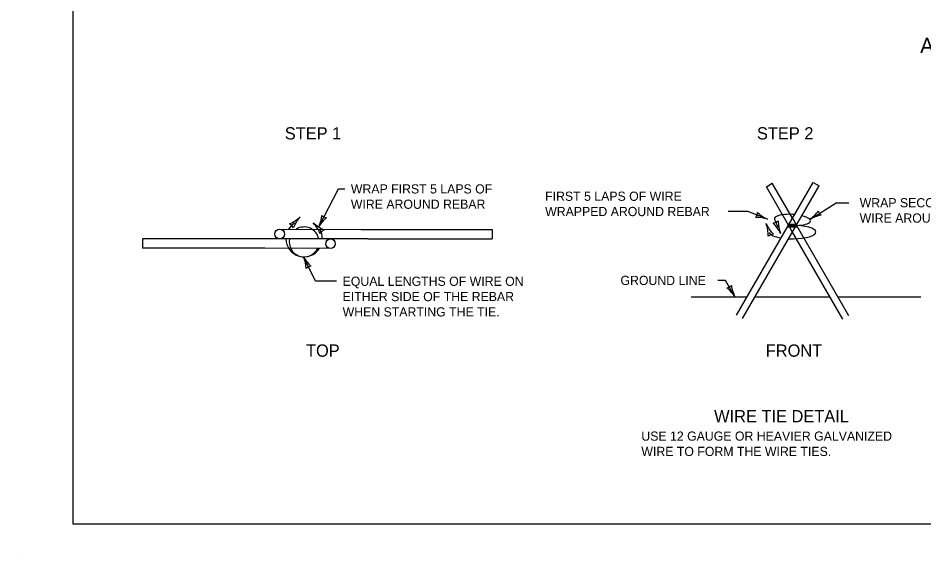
# Model space of a CAD drawing. Extents: x 49991.4 to 50021, y 49987.6 to 50011.4.
# Drawn here: x 49999.02 to 50004.94, y 49987.6 to 49991.1 of the extents above; entities that cross this region are included whole.
import ezdxf

# ---------------------------------------------------------------- set-up
doc = ezdxf.new("R2010")
doc.units = 0
for name, color, linetype in [('Level 1', 7, 'Continuous'), ('Level 2', 7, 'Continuous'), ('Level 3', 7, 'Continuous')]:
    doc.layers.add(name, color=color, linetype=linetype)

msp = doc.modelspace()

# ---------------------------------------------------------------- linework, layer by layer
at = {"layer": 'Level 1'}
for p, q in [((50003.7146, 49989.1648), (50004.2146, 49990.0309)), ((50003.7534, 49989.1424), (50004.2534, 49990.0085)), ((50003.9087, 49990.0035), (50003.9475, 49990.0259)), ((50004.0538, 49989.7523), (50003.9087, 49990.0035)), ((50004.0796, 49989.797), (50003.9475, 49990.0259)), ((50004.2146, 49990.0309), (50004.2534, 49990.0085)), ((50004.0499, 49989.7589), (50004.1093, 49989.7589)), ((50004.0796, 49989.797), (50004.1055, 49989.7522)), ((50000.732, 49989.7258), (50001.2631, 49989.7245)), ((50001.2631, 49989.7245), (50002.1199, 49989.7245)), ((50002.1199, 49989.7245), (50002.1199, 49989.662)), ((50004.0479, 49989.7422), (50004.1113, 49989.7422)), ((50004.0504, 49989.7464), (50004.1088, 49989.7464)), ((50004.0524, 49989.7547), (50004.1069, 49989.7547)), ((50004.0527, 49989.7505), (50004.1065, 49989.7505)), ((50004.0796, 49989.7074), (50004.0538, 49989.7523)), ((50004.4087, 49989.1374), (50004.0796, 49989.7074)), ((50004.4475, 49989.1598), (50004.1055, 49989.7522)), ((50000.627, 49989.6629), (49999.837, 49989.6629)), ((49999.837, 49989.6629), (49999.837, 49989.6019)), ((50001.0638, 49989.6625), (50000.627, 49989.6629)), ((50001.3067, 49989.662), (50000.7322, 49989.6633)), ((50001.3067, 49989.662), (50002.1199, 49989.662)), ((50000.6357, 49989.6019), (49999.837, 49989.6019)), ((50001.0638, 49989.6), (50000.6357, 49989.6019)), ((50003.4178, 49989.2845), (50003.7837, 49989.2845)), ((50003.8354, 49989.2845), (50004.3238, 49989.2845)), ((50004.3755, 49989.2845), (50004.916, 49989.2845)), ((49999.0245, 49987.5988), (49999.0245, 49987.5988))]:
    msp.add_line(p, q, dxfattribs=at)
msp.add_lwpolyline([(49999.3835, 49998.9992), (50016.7501, 49998.9992), (50016.7501, 49987.7988), (49999.3835, 49987.7988)], close=True, dxfattribs=at)
for centre in [(50000.732, 49989.6945), (50001.0638, 49989.6313)]:
    msp.add_circle(centre, 0.0312, dxfattribs=at)
for centre, radius, start, end in [((50000.8914, 49989.6644), 0.1189, 121.84931, 149.00193), ((50000.7017, 49989.9834), 0.2408, 292.89815, 313.08165), ((50000.7687, 49989.7085), 0.0593, 27.58095, 63.30332), ((50001.0546, 49989.6395), 0.2524, 138.26945, 157.5193), ((50000.7748, 49989.603), 0.2408, 22.85111, 43.03462), ((50001.119, 49989.9556), 0.2524, 228.22241, 247.47226), ((50003.6799, 49989.6828), 0.2408, 359.32955, 19.51306), ((50004.1362, 49989.8688), 0.2524, 204.70085, 223.9507), ((50003.9467, 49989.826), 0.0593, 275.32172, 311.04408), ((50003.7745, 49989.5877), 0.2524, 26.01021, 45.26006), ((50004.2265, 49989.784), 0.2408, 180.63891, 200.82242), ((50000.8914, 49989.643), 0.0975, 11.67583, 121.25137), ((50000.8914, 49989.6644), 0.1189, 359.16427, 30.7268), ((50001.0497, 49989.6698), 0.0593, 117.53392, 153.25628), ((50000.8914, 49989.6644), 0.1189, 180.58473, 327.41558), ((50000.8914, 49989.643), 0.0975, 168.07324, 334.11823), ((50003.9587, 49989.6344), 0.0593, 94.01236, 129.73472)]:
    msp.add_arc(centre, radius, start, end, dxfattribs=at)
for centre, major_axis, ratio, start_param, end_param in [((50004.0784, 49989.7872), (0.1177, -0.007), 0.30044, 1.457003, 3.282224), ((50004.0784, 49989.7872), (0.1177, -0.007), 0.30044, 4.967138, 7.309912), ((50004.0796, 49989.7075), (0.1529, -0.0007), 0.289831, 3.244819, 4.209421), ((50004.0796, 49989.7075), (0.1529, -0.0007), 0.289831, 4.548462, 7.680424)]:
    msp.add_ellipse(centre, major_axis=major_axis, ratio=ratio, start_param=start_param, end_param=end_param, dxfattribs=at)
msp.add_spline([(50003.9616, 49989.7892), (50003.9652, 49989.7818), (50003.9847, 49989.7401)], degree=3, dxfattribs=at)
at = {"layer": 'Level 3'}
for p, q in [((50000.9866, 49989.7407), (50001.116, 49989.9892)), ((50001.116, 49989.9892), (50001.1565, 49989.9892)), ((50004.1921, 49989.7903), (50004.3642, 49989.8988)), ((50004.3642, 49989.8988), (50004.4477, 49989.8988)), ((50003.7886, 49989.8414), (50003.66, 49989.8414)), ((50003.9157, 49989.7913), (50003.7886, 49989.8414)), ((50000.9658, 49989.386), (50000.8873, 49989.5455)), ((50001.1027, 49989.386), (50000.9658, 49989.386)), ((50003.643, 49989.3914), (50003.5916, 49989.3914)), ((50003.7036, 49989.2845), (50003.643, 49989.3914))]:
    msp.add_line(p, q, dxfattribs=at)
for centre, radius, start, end in [((50000.7749, 49989.838), 0.233, 335.31457, 354.56442), ((50001.0458, 49989.8544), 0.0548, 224.62608, 260.34844), ((50003.7969, 49989.8381), 0.0548, 320.68734, 356.4097), ((50004.006, 49989.9946), 0.2223, 226.00453, 246.18804), ((50004.0583, 49989.981), 0.233, 305.05449, 324.30434), ((50004.3028, 49989.5975), 0.2223, 99.68319, 119.86669), ((50004.3006, 49989.8587), 0.0548, 194.36599, 230.08836), ((50001.1793, 49989.63), 0.2223, 129.94327, 150.12678), ((50003.8418, 49989.5704), 0.233, 71.37583, 90.62568), ((50000.6839, 49989.4557), 0.2223, 3.66258, 23.84609), ((50001.091, 49989.6586), 0.233, 209.03388, 228.28373), ((50000.9439, 49989.4305), 0.0548, 98.34539, 134.06775), ((50003.6404, 49989.396), 0.0548, 281.68202, 317.40438), ((50003.5068, 49989.1598), 0.233, 32.37051, 51.62036), ((50003.9014, 49989.3861), 0.2223, 186.99921, 207.18272)]:
    msp.add_arc(centre, radius, start, end, dxfattribs=at)

# ---------------------------------------------------------------- texts
at = {"layer": 'Level 2'}
for s, height, p in [('ANCHOR SYSTEM #1', 0.1, (50004.9125, 49990.8761)), ('STEP 1', 0.08, (50000.7653, 49990.3122)), ('STEP 2', 0.08, (50003.8472, 49990.3122)), ('WRAP FIRST 5 LAPS OF', 0.06, (50001.1965, 49989.9592)), ('FIRST 5 LAPS OF WIRE', 0.06, (50002.4647, 49989.9114)), ('WIRE AROUND REBAR', 0.06, (50001.1965, 49989.8592)), ('WRAP SECOND 5 LAPS OF', 0.06, (50004.5177, 49989.8688)), ('WRAPPED AROUND REBAR', 0.06, (50002.4647, 49989.8114)), ('WIRE AROUND FIRST 5 LAPS', 0.06, (50004.5177, 49989.7688)), ('EQUAL LENGTHS OF WIRE ON', 0.06, (50001.1427, 49989.356)), ('GROUND LINE', 0.06, (50002.9564, 49989.3614)), ('EITHER SIDE OF THE REBAR', 0.06, (50001.1427, 49989.256)), ('WHEN STARTING THE TIE.', 0.06, (50001.1427, 49989.156)), ('TOP', 0.08, (50000.9038, 49988.8932)), ('FRONT', 0.08, (50003.9047, 49988.8932)), ('WIRE TIE DETAIL', 0.08, (50003.5677, 49988.4646)), ('USE 12 GAUGE OR HEAVIER GALVANIZED', 0.06, (50003.0926, 49988.3446)), ('WIRE TO FORM THE WIRE TIES.', 0.06, (50003.0926, 49988.2446))]:
    msp.add_text(s, height=height, dxfattribs=at).set_placement(p)

doc.saveas('drawing.dxf')
